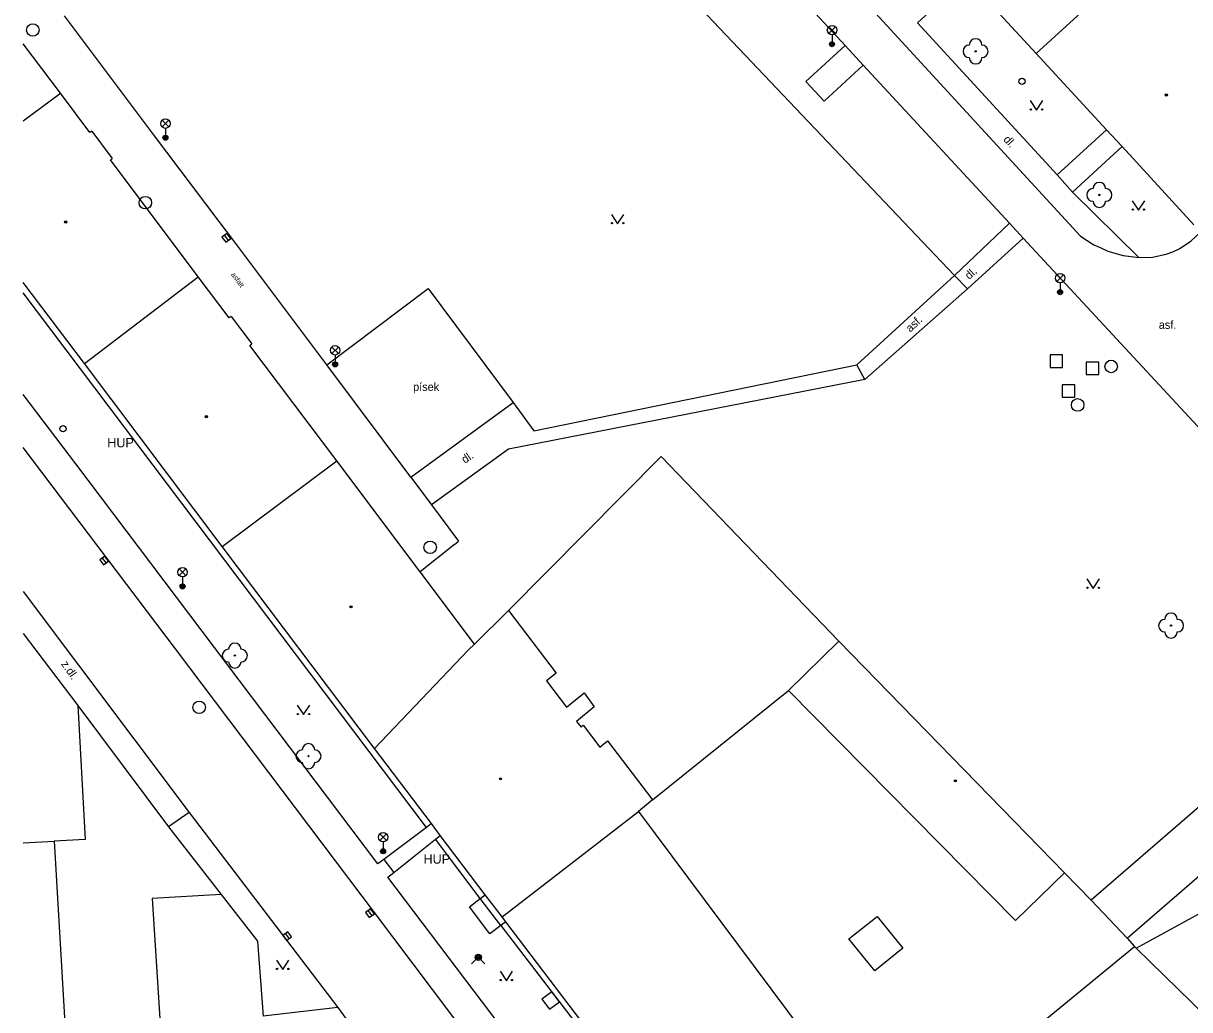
# Model space of a CAD drawing. Extents: x -598932 to -598196, y -1162207 to -1161504.
# Drawn here: x -598932 to -598839, y -1161970.8 to -1161892.2 of the extents above; entities that cross this region are included whole.
import ezdxf

# ---------------------------------------------------------------- set-up
doc = ezdxf.new("R2010")
doc.units = 0
for name, color, linetype in [('DOP - kresba z DSPS bez soueadnic', 7, 'Continuous'), ('Level 22', 7, 'Continuous'), ('Level 26', 7, 'Continuous'), ('Level 27', 7, 'Continuous'), ('Level 28', 7, 'Continuous'), ('Level 31', 7, 'Continuous'), ('Level 33', 7, 'Continuous'), ('Level 36', 7, 'Continuous'), ('Level 39', 7, 'Continuous'), ('specificka linie pasportu komunikaci', 7, 'Continuous'), ('TM - budovy zdene_ betonove - VP', 7, 'Continuous'), ('TM - chodniky - VP', 7, 'Continuous'), ('TM - komunikace - VP', 7, 'Continuous'), ('TM - letecke snimky - pomocna linie', 7, 'Continuous'), ('TM - plot dreveny_ kovovy - VP', 7, 'Continuous'), ('TM - pomocna konstrukcna linie', 7, 'Continuous'), ('TM - popis objektu', 7, 'Continuous'), ('TM - popis povrchu', 7, 'Continuous'), ('TM - rozhrani mezi zpev. plochami mezi sebou - VP', 7, 'Continuous'), ('TM - rozhrani ploch obecne - VP', 7, 'Continuous'), ('TM - vjezd na pozemek', 7, 'Continuous'), ('TM - vstup do budovy - zdene_ betonove', 7, 'Continuous')]:
    doc.layers.add(name, color=color, linetype=linetype)

msp = doc.modelspace()

# ---------------------------------------------------------------- linework, layer by layer
at = {"layer": 'DOP - kresba z DSPS bez soueadnic'}
for points in [[(-598866.17, -1161965.17), (-598863.93, -1161963.4)], [(-598863.93, -1161963.4), (-598861.88, -1161965.92)], [(-598864.1, -1161967.73), (-598866.17, -1161965.17)], [(-598861.88, -1161965.92), (-598864.1, -1161967.73)]]:
    msp.add_lwpolyline(points, dxfattribs=at)
at = {"layer": 'Level 22'}
for centre in [(-598856.07, -1161894.39), (-598846.2, -1161905.84), (-598840.48, -1161940.19), (-598915.15, -1161942.58), (-598909.27, -1161950.6)]:
    msp.add_circle(centre, 0.05, dxfattribs=at)
for centre, start, end in [((-598856.07, -1161893.89), 0, 180), ((-598856.57, -1161894.39), 90, 270), ((-598855.57, -1161894.39), 270, 90), ((-598856.07, -1161894.89), 180, 0), ((-598846.2, -1161905.34), 0, 180), ((-598846.7, -1161905.84), 90, 270), ((-598845.7, -1161905.84), 270, 90), ((-598846.2, -1161906.34), 180, 0), ((-598840.48, -1161939.69), 0, 180), ((-598840.98, -1161940.19), 90, 270), ((-598839.98, -1161940.19), 270, 90), ((-598840.48, -1161940.69), 180, 0), ((-598915.65, -1161942.58), 90, 270), ((-598915.15, -1161942.08), 0, 180), ((-598914.65, -1161942.58), 270, 90), ((-598915.15, -1161943.08), 180, 0), ((-598909.77, -1161950.6), 90, 270), ((-598909.27, -1161950.1), 0, 180), ((-598908.77, -1161950.6), 270, 90), ((-598909.27, -1161951.1), 180, 0)]:
    msp.add_arc(centre, 0.5, start, end, dxfattribs=at)
at = {"layer": 'Level 26'}
for points in [[(-598850.13, -1161919.6), (-598849.13, -1161919.6), (-598849.13, -1161918.6), (-598850.13, -1161918.6)], [(-598847.25, -1161920.17), (-598846.25, -1161920.17), (-598846.25, -1161919.17), (-598847.25, -1161919.17)], [(-598849.16, -1161921.98), (-598848.16, -1161921.98), (-598848.16, -1161920.98), (-598849.16, -1161920.98)], [(-598889.259, -1161970.185), (-598889.865, -1161969.389), (-598890.661, -1161969.995), (-598890.055, -1161970.791)]]:
    msp.add_lwpolyline(points, close=True, dxfattribs=at)
at = {"layer": 'Level 27'}
for p, q in [((-598915.981, -1161909.07), (-598915.679, -1161909.47)), ((-598925.718, -1161934.799), (-598925.422, -1161935.201)), ((-598904.518, -1161962.929), (-598904.222, -1161963.331)), ((-598911.118, -1161964.759), (-598910.822, -1161965.161))]:
    msp.add_line(p, q, dxfattribs=at)
for points in [[(-598916.18, -1161909.221), (-598915.879, -1161909.62), (-598915.48, -1161909.319), (-598915.781, -1161908.92)], [(-598925.92, -1161934.947), (-598925.623, -1161935.35), (-598925.22, -1161935.053), (-598925.517, -1161934.65)], [(-598904.72, -1161963.077), (-598904.423, -1161963.48), (-598904.02, -1161963.183), (-598904.317, -1161962.78)], [(-598911.319, -1161964.907), (-598911.023, -1161965.31), (-598910.62, -1161965.013), (-598910.917, -1161964.61)]]:
    msp.add_lwpolyline(points, close=True, dxfattribs=at)
for centre in [(-598931.26, -1161892.69), (-598922.29, -1161906.46), (-598845.26, -1161919.52), (-598847.93, -1161922.59), (-598899.57, -1161933.95), (-598917.99, -1161946.71)]:
    msp.add_circle(centre, 0.5, dxfattribs=at)
at = {"layer": 'Level 28'}
for centre in [(-598852.36, -1161896.78), (-598928.85, -1161924.48)]:
    msp.add_circle(centre, 0.25, dxfattribs=at)
at = {"layer": 'Level 31'}
msp.add_lwpolyline([(-598896.26, -1161967.17), (-598895.73, -1161966.64), (-598895.2, -1161967.17)], dxfattribs=at)
for radius in [0.25, 0.18, 0.11]:
    msp.add_circle((-598895.73, -1161966.64), radius, dxfattribs=at)
at = {"layer": 'Level 33'}
for p, q in [((-598867.785, -1161892.96), (-598867.255, -1161892.43)), ((-598867.785, -1161892.43), (-598867.255, -1161892.96)), ((-598867.52, -1161893.07), (-598867.52, -1161893.82)), ((-598920.945, -1161900.42), (-598920.415, -1161899.89)), ((-598920.945, -1161899.89), (-598920.415, -1161900.42)), ((-598920.68, -1161900.53), (-598920.68, -1161901.28)), ((-598849.595, -1161912.74), (-598849.065, -1161912.21)), ((-598849.595, -1161912.21), (-598849.065, -1161912.74)), ((-598849.33, -1161912.85), (-598849.33, -1161913.6)), ((-598907.415, -1161918.5), (-598906.885, -1161917.97)), ((-598907.415, -1161917.97), (-598906.885, -1161918.5)), ((-598907.15, -1161918.61), (-598907.15, -1161919.36)), ((-598919.585, -1161936.2), (-598919.055, -1161935.67)), ((-598919.585, -1161935.67), (-598919.055, -1161936.2)), ((-598919.32, -1161936.31), (-598919.32, -1161937.06)), ((-598903.585, -1161957.33), (-598903.055, -1161956.8)), ((-598903.585, -1161956.8), (-598903.055, -1161957.33)), ((-598903.32, -1161957.44), (-598903.32, -1161958.19))]:
    msp.add_line(p, q, dxfattribs=at)
for centre, radius in [((-598867.52, -1161892.695), 0.375), ((-598867.52, -1161893.82), 0.2), ((-598867.52, -1161893.82), 0.145), ((-598867.52, -1161893.82), 0.0876), ((-598920.68, -1161900.155), 0.375), ((-598920.68, -1161901.28), 0.2), ((-598920.68, -1161901.28), 0.145), ((-598920.68, -1161901.28), 0.0876), ((-598849.33, -1161912.475), 0.375), ((-598849.33, -1161913.6), 0.2), ((-598849.33, -1161913.6), 0.145), ((-598849.33, -1161913.6), 0.0876), ((-598907.15, -1161918.235), 0.375), ((-598907.15, -1161919.36), 0.2), ((-598907.15, -1161919.36), 0.145), ((-598907.15, -1161919.36), 0.0876), ((-598919.32, -1161935.935), 0.375), ((-598919.32, -1161937.06), 0.2), ((-598919.32, -1161937.06), 0.145), ((-598919.32, -1161937.06), 0.0876), ((-598903.32, -1161957.065), 0.375), ((-598903.32, -1161958.19), 0.2), ((-598903.32, -1161958.19), 0.145), ((-598903.32, -1161958.19), 0.0876)]:
    msp.add_circle(centre, radius, dxfattribs=at)
at = {"layer": 'Level 36'}
for points in [[(-598851.71, -1161898.32), (-598851.21, -1161899.07), (-598850.71, -1161898.32)], [(-598843.58, -1161906.31), (-598843.08, -1161907.06), (-598842.58, -1161906.31)], [(-598885.12, -1161907.39), (-598884.62, -1161908.14), (-598884.12, -1161907.39)], [(-598847.19, -1161936.47), (-598846.69, -1161937.22), (-598846.19, -1161936.47)], [(-598910.17, -1161946.54), (-598909.67, -1161947.29), (-598909.17, -1161946.54)], [(-598911.83, -1161966.87), (-598911.33, -1161967.62), (-598910.83, -1161966.87)], [(-598893.99, -1161967.76), (-598893.49, -1161968.51), (-598892.99, -1161967.76)]]:
    msp.add_lwpolyline(points, dxfattribs=at)
for centre in [(-598851.66, -1161899.02), (-598850.761, -1161899.02), (-598843.53, -1161907.01), (-598842.631, -1161907.01), (-598885.07, -1161908.09), (-598884.171, -1161908.09), (-598847.14, -1161937.17), (-598846.241, -1161937.17), (-598910.12, -1161947.24), (-598909.221, -1161947.24), (-598911.78, -1161967.57), (-598910.881, -1161967.57), (-598893.94, -1161968.46), (-598893.041, -1161968.46)]:
    msp.add_circle(centre, 0.05, dxfattribs=at)
at = {"layer": 'Level 39'}
for centre, radius in [((-598840.86, -1161897.88), 0.09), ((-598840.86, -1161897.88), 0.0398), ((-598928.63, -1161907.99), 0.09), ((-598928.63, -1161907.99), 0.0398), ((-598917.43, -1161923.52), 0.09), ((-598917.43, -1161923.52), 0.0398), ((-598905.88, -1161938.69), 0.09), ((-598905.88, -1161938.69), 0.0398), ((-598893.96, -1161952.41), 0.09), ((-598893.96, -1161952.41), 0.0398), ((-598857.68, -1161952.57), 0.09), ((-598857.68, -1161952.57), 0.0398)]:
    msp.add_circle(centre, radius, dxfattribs=at)
at = {"layer": 'specificka linie pasportu komunikaci'}
for points in [[(-598865.03, -1161895.48), (-598868.135, -1161898.364), (-598869.612, -1161896.794), (-598866.47, -1161893.92)], [(-598849.57, -1161904.24), (-598848.35, -1161905.62)], [(-598903.27, -1161958.84), (-598902.47, -1161959.88)], [(-598893.941, -1161964.111), (-598895.57, -1161961.96)], [(-598893.941, -1161964.111), (-598885.29, -1161975.39)]]:
    msp.add_lwpolyline(points, dxfattribs=at)
at = {"layer": 'TM - budovy zdene_ betonove - VP'}
for points in [[(-598851.24, -1161894.56), (-598856.8, -1161888.53)], [(-598844.96, -1161888.82), (-598851.24, -1161894.56)], [(-598926.56, -1161900.76), (-598926.7, -1161900.86), (-598929.06, -1161897.72), (-598932.017, -1161893.793)], [(-598845.64, -1161900.64), (-598851.24, -1161894.56)], [(-598932.017, -1161899.934), (-598929.06, -1161897.72)], [(-598844.39, -1161901.99), (-598845.64, -1161900.64)], [(-598838.65, -1161908.22), (-598844.39, -1161901.99)], [(-598915.44, -1161915.53), (-598915.59, -1161915.65), (-598918.06, -1161912.37), (-598925.06, -1161903.05), (-598924.92, -1161902.94)], [(-598927.15, -1161919.28), (-598932.017, -1161912.817)], [(-598927.15, -1161919.28), (-598918.06, -1161912.37)], [(-598896.03, -1161941.66), (-598900.36, -1161935.89), (-598907.01, -1161927.05), (-598913.94, -1161917.84), (-598913.79, -1161917.73)], [(-598916.16, -1161933.87), (-598927.15, -1161919.28)], [(-598916.16, -1161933.87), (-598907.01, -1161927.05)], [(-598904.02, -1161949.98), (-598916.16, -1161933.87)], [(-598896.5, -1161942.13), (-598896.03, -1161941.66), (-598893.33, -1161938.99)], [(-598893.33, -1161938.99), (-598889.53, -1161943.97)], [(-598932.017, -1161940.825), (-598927.66, -1161946.56)], [(-598866.97, -1161941.44), (-598871, -1161945.36)], [(-598848.98, -1161959.91), (-598866.97, -1161941.44)], [(-598904.02, -1161949.98), (-598896.5, -1161942.13)], [(-598889.53, -1161943.97), (-598890.3, -1161944.59)], [(-598890.3, -1161944.59), (-598888.69, -1161946.7)], [(-598888.69, -1161946.7), (-598887.3, -1161945.55)], [(-598887.3, -1161945.55), (-598886.49, -1161946.67)], [(-598871, -1161945.36), (-598852.89, -1161963.72)], [(-598927.66, -1161946.56), (-598927.08, -1161957.24)], [(-598886.49, -1161946.67), (-598887.89, -1161947.84)], [(-598887.89, -1161947.84), (-598887.52, -1161948.29)], [(-598887.52, -1161948.29), (-598887.37, -1161948.14)], [(-598887.37, -1161948.14), (-598886.03, -1161949.88)], [(-598886.03, -1161949.88), (-598885.42, -1161949.38)], [(-598885.42, -1161949.38), (-598881.85, -1161954.09)], [(-598899.47, -1161955.98), (-598904.02, -1161949.98)], [(-598881.85, -1161954.09), (-598882.96, -1161955.02)], [(-598893.84, -1161963.41), (-598882.96, -1161955.02)], [(-598882.96, -1161955.02), (-598863.18, -1161981.51)], [(-598898.76, -1161956.92), (-598899.47, -1161955.98)], [(-598893.84, -1161963.41), (-598895.17, -1161961.66), (-598898.76, -1161956.92)], [(-598932.017, -1161957.521), (-598929.55, -1161957.38)], [(-598927.08, -1161957.24), (-598929.55, -1161957.38)], [(-598929.55, -1161957.38), (-598927.4, -1161994.12)], [(-598852.89, -1161963.72), (-598848.98, -1161959.91)], [(-598884.94, -1161975.11), (-598893.54, -1161963.81), (-598893.84, -1161963.41)]]:
    msp.add_lwpolyline(points, dxfattribs=at)
at = {"layer": 'TM - chodniky - VP'}
for points in [[(-598856.8, -1161888.53), (-598860.69, -1161892.12), (-598849.57, -1161904.24), (-598845.64, -1161900.64)], [(-598844.39, -1161901.99), (-598848.35, -1161905.62), (-598843.06, -1161910.84)], [(-598857.74, -1161912.28), (-598853.37, -1161908.08)], [(-598852.28, -1161909.3), (-598856.72, -1161913.34)], [(-598865.55, -1161919.4), (-598857.74, -1161912.28)], [(-598907.8, -1161919.4), (-598899.72, -1161913.3), (-598892.96, -1161922.4)], [(-598856.72, -1161913.34), (-598864.9, -1161920.57)], [(-598892.96, -1161922.4), (-598891.29, -1161924.65), (-598865.55, -1161919.4)], [(-598864.9, -1161920.57), (-598893.33, -1161926.12), (-598899.47, -1161930.55)], [(-598899.87, -1161956.28), (-598903.27, -1161958.84), (-598903.74, -1161959.2), (-598915.78, -1161943.25), (-598927.82, -1161927.29), (-598932.017, -1161921.76)], [(-598824.1, -1161946.21), (-598827.18, -1161946.79), (-598829.97, -1161947.49), (-598846.86, -1161962.1)], [(-598843.98, -1161965.11), (-598830.09, -1161953.1), (-598831.9, -1161956.56), (-598833.48, -1161957.83), (-598832.33, -1161959.93)], [(-598918.8, -1161955.1), (-598920.44, -1161956.24)], [(-598899.47, -1161955.98), (-598899.87, -1161956.28)], [(-598899.15, -1161957.23), (-598898.76, -1161956.92)], [(-598884.94, -1161975.11), (-598885.29, -1161975.39), (-598889.18, -1161978.44), (-598902.94, -1161960.25), (-598902.47, -1161959.88), (-598899.15, -1161957.23)], [(-598906.94, -1161970.64), (-598912.89, -1161971.34)]]:
    msp.add_lwpolyline(points, dxfattribs=at)
at = {"layer": 'TM - komunikace - VP'}
for points in [[(-598900.7, -1161851.45), (-598847.71, -1161909.14)], [(-598886.7, -1161872.05), (-598884.42, -1161874.52), (-598883, -1161876.05), (-598866.47, -1161893.92), (-598865.03, -1161895.48), (-598853.37, -1161908.08)], [(-598901.12, -1161928.35), (-598907.8, -1161919.4), (-598915.24, -1161909.5), (-598916.41, -1161907.97), (-598921.64, -1161901.03), (-598928.74, -1161891.57)], [(-598853.37, -1161908.08), (-598852.28, -1161909.3)], [(-598852.28, -1161909.3), (-598824.79, -1161938.92)], [(-598847.71, -1161909.14), (-598846.65, -1161909.809), (-598846.145, -1161910.035), (-598845.51, -1161910.32), (-598844.302, -1161910.667), (-598843.06, -1161910.84)], [(-598843.06, -1161910.84), (-598841.95, -1161910.805), (-598840.865, -1161910.571), (-598840.34, -1161910.38), (-598839.84, -1161910.145), (-598838.908, -1161909.541), (-598838.1, -1161908.78)], [(-598889.25, -1161982.64), (-598889.89, -1161981.82), (-598904.1, -1161962.96), (-598904.99, -1161961.76), (-598919.88, -1161942.03), (-598925.34, -1161934.83), (-598932.017, -1161925.987)], [(-598897.64, -1161933.73), (-598900.36, -1161935.89)], [(-598932.017, -1161937.478), (-598918.8, -1161955.1)], [(-598918.8, -1161955.1), (-598906.94, -1161970.64)], [(-598906.94, -1161970.64), (-598901.06, -1161978.72)]]:
    msp.add_lwpolyline(points, dxfattribs=at)
at = {"layer": 'TM - letecke snimky - pomocna linie'}
for points in [[(-598881.85, -1161954.09), (-598871, -1161945.36)], [(-598916.23, -1161961.64), (-598921.73, -1161961.95), (-598921.1, -1161971.94)]]:
    msp.add_lwpolyline(points, dxfattribs=at)
at = {"layer": 'TM - plot dreveny_ kovovy - VP'}
for points in [[(-598893.33, -1161938.99), (-598881.14, -1161926.71)], [(-598881.14, -1161926.71), (-598866.97, -1161941.44)], [(-598927.66, -1161946.56), (-598920.44, -1161956.24)], [(-598920.44, -1161956.24), (-598916.23, -1161961.64), (-598913.34, -1161965.35), (-598912.89, -1161971.34)], [(-598843.27, -1161965.91), (-598832.33, -1161959.93)], [(-598843.98, -1161965.11), (-598843.39, -1161965.78)], [(-598843.39, -1161965.78), (-598843.27, -1161965.91)]]:
    msp.add_lwpolyline(points, dxfattribs=at)
at = {"layer": 'TM - pomocna konstrukcna linie'}
for points in [[(-598901.12, -1161928.35), (-598899.47, -1161930.55), (-598897.3, -1161933.46)], [(-598897.64, -1161933.73), (-598897.3, -1161933.46)]]:
    msp.add_lwpolyline(points, dxfattribs=at)
at = {"layer": 'TM - rozhrani mezi zpev. plochami mezi sebou - VP'}
msp.add_lwpolyline([(-598893.18, -1161874.95), (-598857.74, -1161912.28)], dxfattribs=at)
at = {"layer": 'TM - rozhrani ploch obecne - VP'}
for points in [[(-598857.74, -1161912.28), (-598856.72, -1161913.34)], [(-598899.87, -1161956.28), (-598932.017, -1161913.644)], [(-598864.9, -1161920.57), (-598865.55, -1161919.4)], [(-598901.12, -1161928.35), (-598892.96, -1161922.4)], [(-598895.57, -1161961.96), (-598899.15, -1161957.23)], [(-598893.54, -1161963.81), (-598893.941, -1161964.111), (-598894.82, -1161964.77), (-598896.44, -1161962.61), (-598895.57, -1161961.96)], [(-598895.57, -1161961.96), (-598895.17, -1161961.66)], [(-598853.91, -1161974.42), (-598843.39, -1161965.78)], [(-598843.27, -1161965.91), (-598829.92, -1161978.95), (-598829.55, -1161985.5)]]:
    msp.add_lwpolyline(points, dxfattribs=at)
at = {"layer": 'TM - vjezd na pozemek'}
for points in [[(-598846.86, -1161962.1), (-598848.98, -1161959.91)], [(-598843.98, -1161965.11), (-598846.86, -1161962.1)]]:
    msp.add_lwpolyline(points, dxfattribs=at)
at = {"layer": 'TM - vstup do budovy - zdene_ betonove'}
for points in [[(-598926.56, -1161900.76), (-598924.92, -1161902.94)], [(-598915.44, -1161915.53), (-598913.79, -1161917.73)]]:
    msp.add_lwpolyline(points, dxfattribs=at)

# ---------------------------------------------------------------- texts
at = {"layer": 'TM - popis objektu'}
for p in [(-598925.32, -1161925.97), (-598900.1, -1161959.18)]:
    msp.add_text('HUP', height=0.75, dxfattribs=at).set_placement(p)
at = {"layer": 'TM - popis povrchu'}
for s, height, rotation, p in [('dl.', 0.65, 312.09, (-598853.9, -1161901.45)), ('asfalt', 0.4, 305.90217, (-598915.47, -1161912.19)), ('dl.', 0.65, 41.82, (-598856.58, -1161912.63)), ('asf.', 0.65, 43, (-598861.28, -1161916.83)), ('dl.', 0.65, 34.08, (-598896.8, -1161927.29)), ('z.dl.', 0.65, 304.32, (-598929.03, -1161943.25))]:
    msp.add_text(s, height=height, rotation=rotation, dxfattribs=at).set_placement(p)
for s, p in [('asf.', (-598841.46, -1161916.52)), ('písek', (-598900.93, -1161921.47))]:
    msp.add_text(s, height=0.65, dxfattribs=at).set_placement(p)

doc.saveas('drawing.dxf')
